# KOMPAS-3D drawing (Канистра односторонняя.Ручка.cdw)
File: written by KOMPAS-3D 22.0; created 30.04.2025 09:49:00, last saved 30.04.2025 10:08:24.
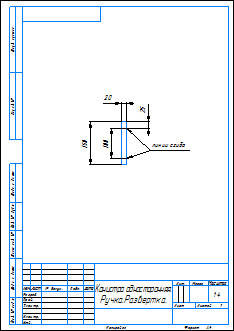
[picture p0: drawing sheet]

Sheet 1: A4, portrait

Document properties: Автор: Admin; Наименование: Канистра односторонняя. Ручка.Развертка; Полное имя файла: D:\28.11.2016\3D модели\Абилимпикс\2025\Канистра односторонняя\Канистра односторонняя.Ручка.cdw

Title block, sheet 1: Наименование: Канистра односторонняя. / Ручка.Развертка.; scale: 1:4; Количество листов документа: 1; Форматы листов документа: A4; stored path: D:\28.11.2016\3D модели\Абилимпикс\2025\Канистра односторонняя\Канистра односторонняя.Зад.cdw

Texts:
  линии сгиба
Dimensions and other numbers on the sheet: 150; 20; 25; 100; 1:4; 1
